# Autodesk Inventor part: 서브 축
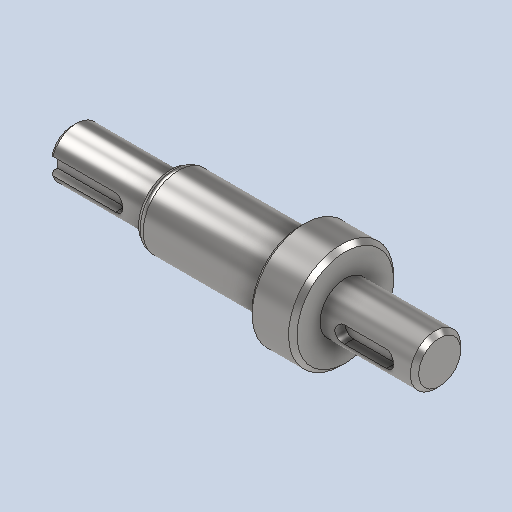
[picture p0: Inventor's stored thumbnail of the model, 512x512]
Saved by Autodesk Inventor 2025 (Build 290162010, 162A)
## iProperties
Created: 2024-07
Part Number: 서브 축
Material: 강철, 연강
Document SubType Name: Modeling
Designer: Admin
Density: 7.86 g/cm^3
Appearance: 기본값
Author: jhkim
Revision Number: 1
Sending System: Autodesk Inventor 2025
Preprocessor: ST-DEVELOPER v20
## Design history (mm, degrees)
feature "솔리드1"
node "솔리드2"
